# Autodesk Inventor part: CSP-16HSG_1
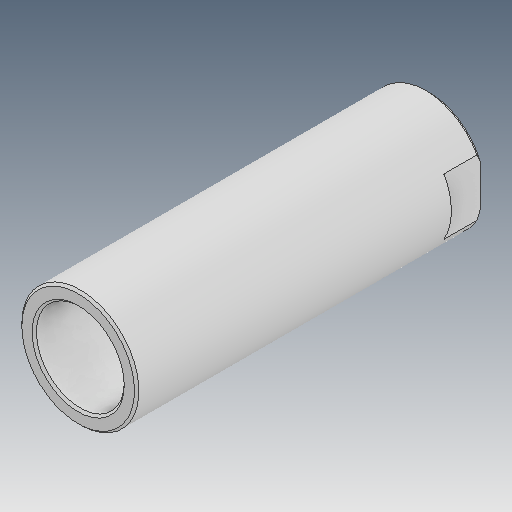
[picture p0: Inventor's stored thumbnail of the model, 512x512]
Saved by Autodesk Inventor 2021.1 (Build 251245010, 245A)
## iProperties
Created: 2021-06
Part Number: CSP-16HSG_1
Material: Ogólny
Document SubType Name: Modeling
Designer: user
Density: 1 g/cm^3
Appearance: Domyślna
Author: user
Revision Number: ÈÎºÎ
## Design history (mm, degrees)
feature "ÊäÈë1"
node "Bryła1"
